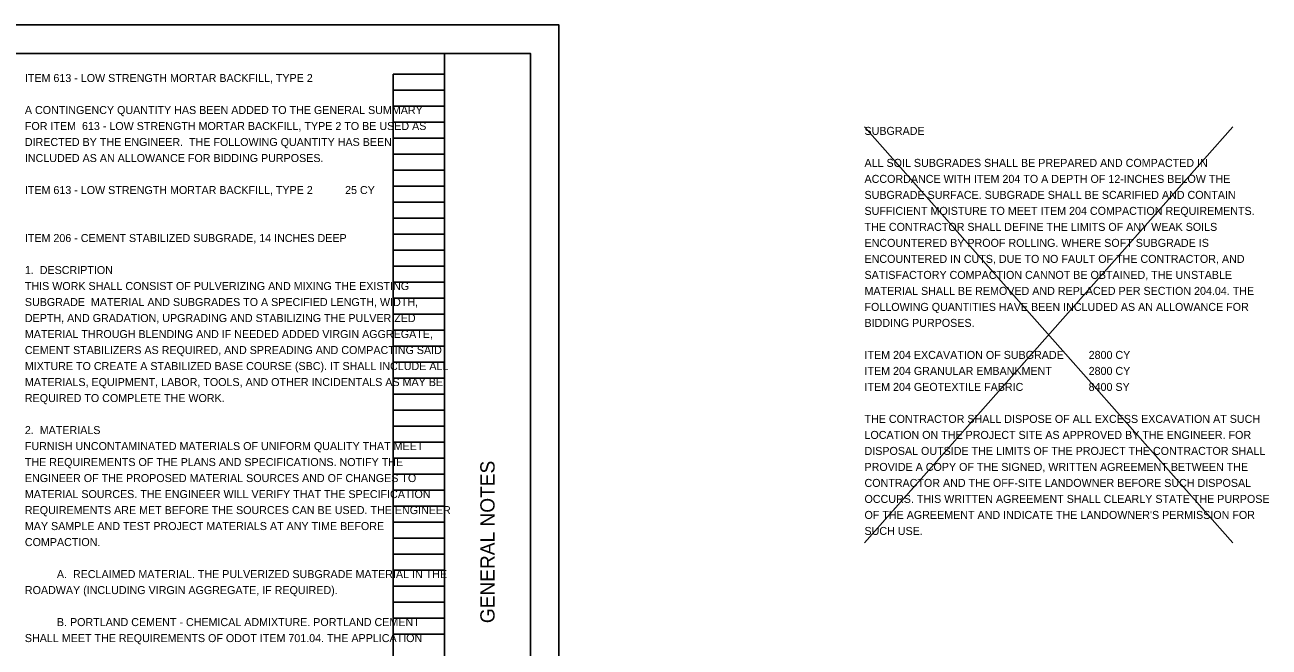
# Model space of a CAD drawing. Extents: x 0 to 46.4, y 0 to 22.
# Drawn here: x 24.66 to 46.42, y 11.11 to 22 of the extents above; entities that cross this region are included whole.
import ezdxf

# ---------------------------------------------------------------- set-up
doc = ezdxf.new("R2010")
doc.units = 0
for name, color, linetype in [('SH_Border', 7, 'Continuous'), ('SH_Cut_Line', 7, 'Continuous'), ('SH_Data', 7, 'Continuous'), ('SH_Text', 7, 'Continuous')]:
    doc.layers.add(name, color=color, linetype=linetype)

msp = doc.modelspace()

# ---------------------------------------------------------------- linework, layer by layer
at = {"layer": 'SH_Border'}
msp.add_line((32, 0.5), (32, 21.5), dxfattribs=at)
msp.add_lwpolyline([(1.5, 21.5), (33.5, 21.5), (33.5, 0.5), (1.5, 0.5)], close=True, dxfattribs=at)
at = {"layer": 'SH_Cut_Line'}
msp.add_lwpolyline([(0, 0), (34, 0), (34, 22), (0, 22)], close=True, dxfattribs=at)
at = {"layer": 'SH_Data'}
for p, q in [((31.1, 0.98), (31.1, 21.14)), ((31.1, 21.14), (32, 21.14)), ((32, 0.98), (32, 21.14)), ((31.1, 20.86), (32, 20.86)), ((31.1, 20.58), (32, 20.58)), ((31.1, 20.3), (32, 20.3)), ((31.1, 20.02), (32, 20.02)), ((31.1, 19.74), (32, 19.74)), ((31.1, 19.46), (32, 19.46)), ((31.1, 19.18), (32, 19.18)), ((31.1, 18.9), (32, 18.9)), ((31.1, 18.62), (32, 18.62)), ((31.1, 18.34), (32, 18.34)), ((31.1, 18.06), (32, 18.06)), ((31.1, 17.78), (32, 17.78)), ((31.1, 17.5), (32, 17.5)), ((31.1, 17.22), (32, 17.22)), ((31.1, 16.94), (32, 16.94)), ((31.1, 16.66), (32, 16.66)), ((31.1, 16.38), (32, 16.38)), ((31.1, 16.1), (32, 16.1)), ((31.1, 15.82), (32, 15.82)), ((31.1, 15.54), (32, 15.54)), ((31.1, 15.26), (32, 15.26)), ((31.1, 14.98), (32, 14.98)), ((31.1, 14.7), (32, 14.7)), ((31.1, 14.42), (32, 14.42)), ((31.1, 14.14), (32, 14.14)), ((31.1, 13.86), (32, 13.86)), ((31.1, 13.58), (32, 13.58)), ((31.1, 13.3), (32, 13.3)), ((31.1, 13.02), (32, 13.02)), ((31.1, 12.74), (32, 12.74)), ((31.1, 12.46), (32, 12.46)), ((31.1, 12.18), (32, 12.18)), ((31.1, 11.9), (32, 11.9)), ((31.1, 11.62), (32, 11.62)), ((31.1, 11.34), (32, 11.34))]:
    msp.add_line(p, q, dxfattribs=at)
at = {"layer": 'SH_Text'}
for p, q in [((39.344, 20.215), (45.784, 12.935)), ((45.784, 20.215), (39.344, 12.935))]:
    msp.add_line(p, q, dxfattribs=at)

# ---------------------------------------------------------------- texts
at = {"layer": 'SH_Data'}
msp.add_text('GENERAL NOTES', height=0.25, rotation=90, dxfattribs=at).set_placement((32.875, 11.531))
at = {"layer": 'SH_Text'}
for s, p in [('ITEM 613 - LOW STRENGTH MORTAR BACKFILL, TYPE 2', (24.66, 21)), ('A CONTINGENCY QUANTITY HAS BEEN ADDED TO THE GENERAL SUMMARY', (24.66, 20.44)), ('FOR ITEM  613 - LOW STRENGTH MORTAR BACKFILL, TYPE 2 TO BE USED AS ', (24.66, 20.16)), ('DIRECTED BY THE ENGINEER.  THE FOLLOWING QUANTITY HAS BEEN ', (24.66, 19.88)), ('SUBGRADE', (39.344, 20.075)), ('INCLUDED AS AN ALLOWANCE FOR BIDDING PURPOSES.', (24.66, 19.6)), ('ALL SOIL SUBGRADES SHALL BE PREPARED AND COMPACTED IN ', (39.344, 19.515)), ('ACCORDANCE WITH ITEM 204 TO A DEPTH OF 12-INCHES BELOW THE ', (39.344, 19.235)), ('ITEM 613 - LOW STRENGTH MORTAR BACKFILL, TYPE 2 ', (24.66, 19.04)), ('25 CY', (30.26, 19.04)), ('SUBGRADE SURFACE. SUBGRADE SHALL BE SCARIFIED AND CONTAIN ', (39.344, 18.955)), ('SUFFICIENT MOISTURE TO MEET ITEM 204 COMPACTION REQUIREMENTS.', (39.344, 18.675)), ('THE CONTRACTOR SHALL DEFINE THE LIMITS OF ANY WEAK SOILS ', (39.344, 18.395)), ('ITEM 206 - CEMENT STABILIZED SUBGRADE, 14 INCHES DEEP', (24.66, 18.2)), ('ENCOUNTERED BY PROOF ROLLING. WHERE SOFT SUBGRADE IS ', (39.344, 18.115)), ('ENCOUNTERED IN CUTS, DUE TO NO FAULT OF THE CONTRACTOR, AND ', (39.344, 17.835)), ('1.  DESCRIPTION', (24.66, 17.64)), ('SATISFACTORY COMPACTION CANNOT BE OBTAINED, THE UNSTABLE ', (39.344, 17.555)), ('THIS WORK SHALL CONSIST OF PULVERIZING AND MIXING THE EXISTING ', (24.66, 17.36)), ('MATERIAL SHALL BE REMOVED AND REPLACED PER SECTION 204.04. THE ', (39.344, 17.275)), ('SUBGRADE  MATERIAL AND SUBGRADES TO A SPECIFIED LENGTH, WIDTH, ', (24.66, 17.08)), ('FOLLOWING QUANTITIES HAVE BEEN INCLUDED AS AN ALLOWANCE FOR ', (39.344, 16.995)), ('DEPTH, AND GRADATION, UPGRADING AND STABILIZING THE PULVERIZED ', (24.66, 16.8)), ('BIDDING PURPOSES.', (39.344, 16.715)), ('MATERIAL THROUGH BLENDING AND IF NEEDED ADDED VIRGIN AGGREGATE, ', (24.66, 16.52)), ('CEMENT STABILIZERS AS REQUIRED, AND SPREADING AND COMPACTING SAID ', (24.66, 16.24)), ('MIXTURE TO CREATE A STABILIZED BASE COURSE (SBC). IT SHALL INCLUDE ALL ', (24.66, 15.96)), ('ITEM 204 EXCAVATION OF SUBGRADE', (39.344, 16.155)), ('2800 CY', (43.264, 16.155)), ('ITEM 204 GRANULAR EMBANKMENT', (39.344, 15.875)), ('2800 CY', (43.264, 15.875)), ('MATERIALS, EQUIPMENT, LABOR, TOOLS, AND OTHER INCIDENTALS AS MAY BE ', (24.66, 15.68)), ('ITEM 204 GEOTEXTILE FABRIC', (39.344, 15.595)), ('8400 SY', (43.264, 15.595)), ('REQUIRED TO COMPLETE THE WORK.', (24.66, 15.4)), ('THE CONTRACTOR SHALL DISPOSE OF ALL EXCESS EXCAVATION AT SUCH ', (39.344, 15.035)), ('2.  MATERIALS', (24.66, 14.84)), ('LOCATION ON THE PROJECT SITE AS APPROVED BY THE ENGINEER. FOR ', (39.344, 14.755)), ('FURNISH UNCONTAMINATED MATERIALS OF UNIFORM QUALITY THAT MEET ', (24.66, 14.56)), ('DISPOSAL OUTSIDE THE LIMITS OF THE PROJECT THE CONTRACTOR SHALL ', (39.344, 14.475)), ('THE REQUIREMENTS OF THE PLANS AND SPECIFICATIONS. NOTIFY THE ', (24.66, 14.28)), ('PROVIDE A COPY OF THE SIGNED, WRITTEN AGREEMENT BETWEEN THE ', (39.344, 14.195)), ('ENGINEER OF THE PROPOSED MATERIAL SOURCES AND OF CHANGES TO ', (24.66, 14)), ('CONTRACTOR AND THE OFF-SITE LANDOWNER BEFORE SUCH DISPOSAL ', (39.344, 13.915)), ('MATERIAL SOURCES. THE ENGINEER WILL VERIFY THAT THE SPECIFICATION ', (24.66, 13.72)), ('OCCURS. THIS WRITTEN AGREEMENT SHALL CLEARLY STATE THE PURPOSE ', (39.344, 13.635)), ('REQUIREMENTS ARE MET BEFORE THE SOURCES CAN BE USED. THE ENGINEER ', (24.66, 13.44)), ("OF THE AGREEMENT AND INDICATE THE LANDOWNER'S PERMISSION FOR ", (39.344, 13.355)), ('MAY SAMPLE AND TEST PROJECT MATERIALS AT ANY TIME BEFORE ', (24.66, 13.16)), ('SUCH USE.', (39.344, 13.075)), ('COMPACTION.', (24.66, 12.88)), ('A.  RECLAIMED MATERIAL. THE PULVERIZED SUBGRADE MATERIAL IN THE ', (25.22, 12.32)), ('ROADWAY (INCLUDING VIRGIN AGGREGATE, IF REQUIRED).', (24.66, 12.04)), ('B. PORTLAND CEMENT - CHEMICAL ADMIXTURE. PORTLAND CEMENT ', (25.22, 11.48)), ('SHALL MEET THE REQUIREMENTS OF ODOT ITEM 701.04. THE APPLICATION ', (24.66, 11.2))]:
    msp.add_text(s, height=0.14, dxfattribs=at).set_placement(p)

doc.saveas('drawing.dxf')
